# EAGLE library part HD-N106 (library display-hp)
LED DISPLAY + - 1/2 character, decimal point right
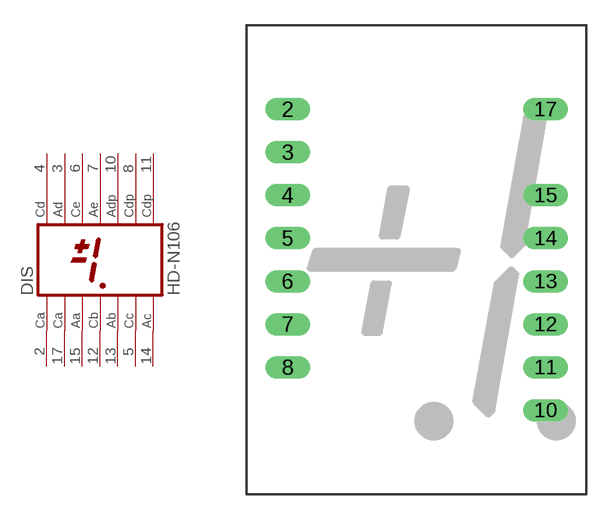
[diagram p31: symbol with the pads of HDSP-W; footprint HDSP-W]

Designator prefix DIS

## HD-N106 (OC_FARNELL: unknown; OC_NEWARK: unknown)  [HDSP-W]
2  CA  pas
3  AD  pas
4  CD  pas
5  CC  pas
6  CE  pas
7  AE  pas
8  CDP  pas
10  ADP  pas
11  CDP  pas
12  CB  pas
13  AB  pas
14  AC  pas
15  AA  pas
17  CA  pas

## Footprint HDSP-W (pad centres in mm)
LED DISPLAY 20-mm + - 1/2 character, 2 decimal points
drill 0.813 long: 2 -7.62,8.89; 3 -7.62,6.35; 4 -7.62,3.81; 5 -7.62,1.27; 6 -7.62,-1.27; 7 -7.62,-3.81; 8 -7.62,-6.35; 10 7.62,-8.89; 11 7.62,-6.35; 12 7.62,-3.81; 13 7.62,-1.27; 14 7.62,1.27; 15 7.62,3.81; 17 7.62,8.89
